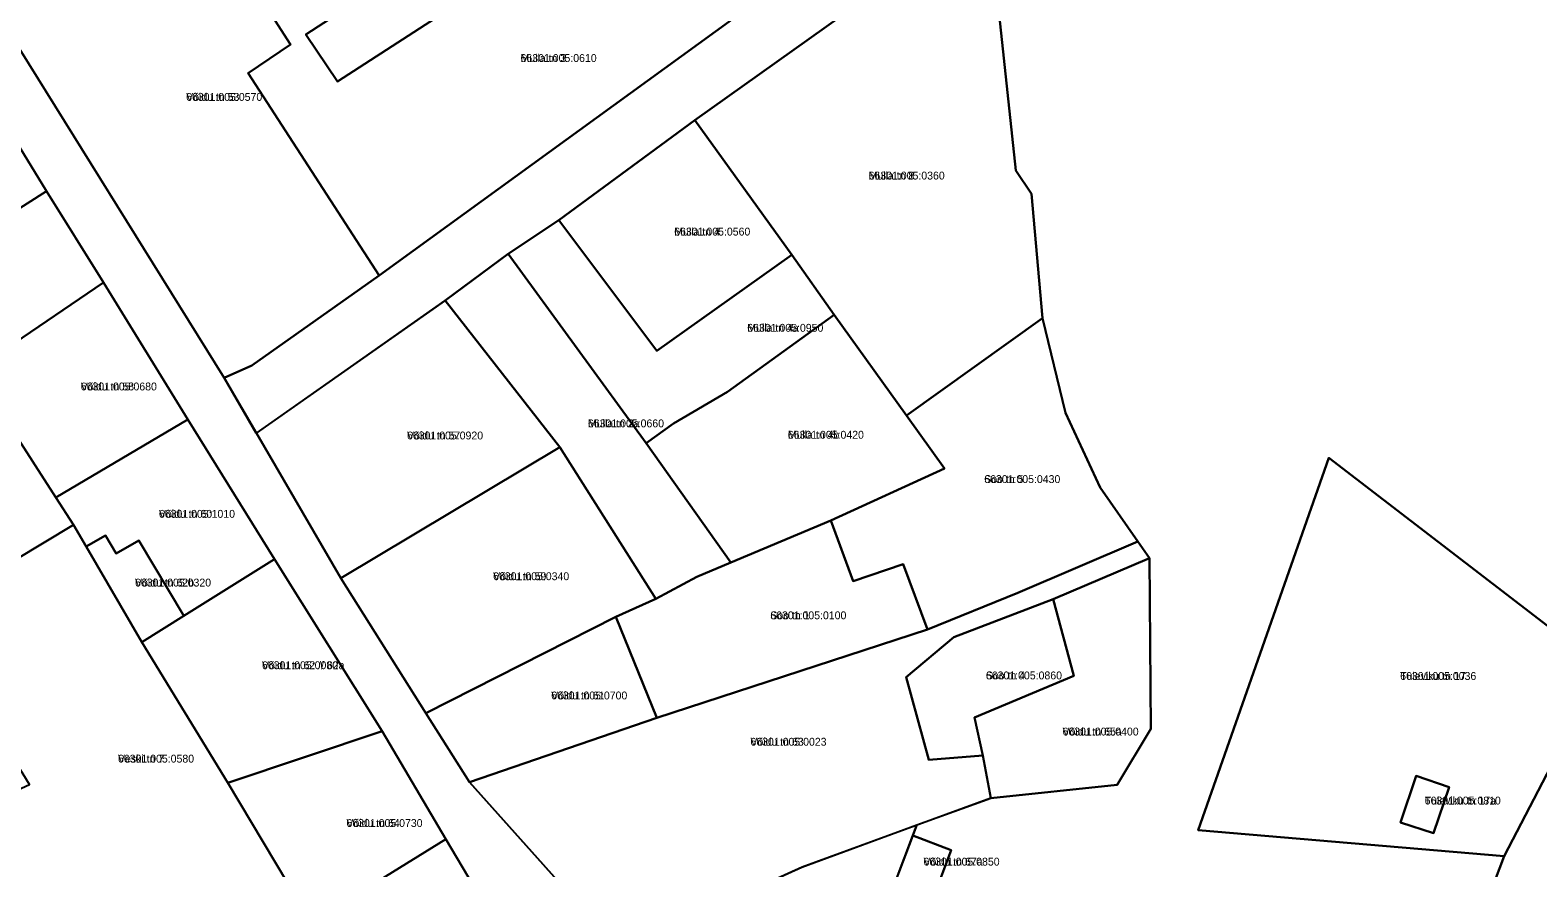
# Model space of a CAD drawing. Extents: x 632278 to 636344, y 6578401 to 6583362.
# Drawn here: x 634584.8 to 634872.1, y 6581260.6 to 6581420.2 of the extents above; entities that cross this region are included whole.
import ezdxf

# ---------------------------------------------------------------- set-up
doc = ezdxf.new("R2010")
doc.units = 0
for name, color, linetype in [('L_AADRESS', 7, 'Continuous'), ('PIIR', 7, 'Continuous'), ('TUNNUS', 7, 'Continuous')]:
    doc.layers.add(name, color=color, linetype=linetype)

msp = doc.modelspace()

# ---------------------------------------------------------------- linework, layer by layer
at = {"layer": 'PIIR'}
for points in [[(634366.06, 6581761.71), (634390.59, 6581723.7), (634395.02, 6581716.06), (634412.03, 6581688.4), (634425.76, 6581666.4), (634429.3, 6581660.73), (634446.2, 6581633.64), (634465.25, 6581603.88), (634470.5, 6581595.28), (634490.9, 6581563.22), (634504.23, 6581541.92), (634512.73, 6581527.76), (634519.26, 6581517.48), (634520.6, 6581515.15), (634532.79, 6581495.33), (634537.33, 6581488.04), (634558.25, 6581454.99), (634577.69, 6581424.67), (634621.73, 6581353.95), (634627.88, 6581343.38), (634643.98, 6581315.73), (634660.16, 6581290.01), (634668.51, 6581276.9), (634697.09, 6581244.95)], [(634840.08, 6581195.15), (634865.69, 6581262.77), (634884.36, 6581298.68), (634901.59, 6581345.02), (634942.3, 6581443.99), (634957.44, 6581478.78), (635000.2, 6581574.59), (635013.75, 6581602.14), (635016.6, 6581620.48), (635049.2, 6581605.85), (635026.32, 6581551.66), (634952.62, 6581376.82), (634946.53, 6581362.44), (634912.6, 6581276.11), (634918.34, 6581271.91), (634893.28, 6581244.04)], [(634757.02, 6581255.3), (634760.32, 6581263.95), (634752.99, 6581266.7), (634753.73, 6581268.73), (634767.88, 6581273.86), (634791.94, 6581276.36), (634798.32, 6581287.05), (634798.08, 6581319.59), (634795.84, 6581322.71), (634788.66, 6581333.04), (634782.11, 6581347.23), (634777.69, 6581365.33), (634775.6, 6581389.02), (634772.59, 6581393.46), (634767.34, 6581442.85), (634759.62, 6581513.31), (634774.57, 6581515.21), (634814.93, 6581519.91), (634841.41, 6581536.87), (634880.57, 6581561.87)], [(634767.34, 6581442.86), (634711.44, 6581403.03), (634685.54, 6581383.96), (634675.87, 6581377.55), (634663.83, 6581368.64), (634627.87, 6581343.39), (634621.72, 6581353.95), (634627.04, 6581356.26), (634651.31, 6581373.43), (634725.1, 6581427.07)], [(634674.56, 6581248.21), (634663.99, 6581266.03), (634651.83, 6581286.57), (634631.34, 6581319.38), (634614.8, 6581345.96), (634598.74, 6581372.09), (634587.89, 6581389.49), (634576.29, 6581408.42)], [(634884.36, 6581298.68), (634832.26, 6581338.69), (634807.36, 6581267.76), (634865.69, 6581262.77), (634840.08, 6581195.15)]]:
    msp.add_lwpolyline(points, dxfattribs=at)
for points in [[(634637.29, 6581419.37), (634652.51, 6581429.29), (634678.14, 6581446.22), (634706.81, 6581465.37), (634737.46, 6581485.56), (634726.44, 6581431.65), (634711.98, 6581454.81), (634643.37, 6581410.37)], [(634632.85, 6581459.43), (634644.18, 6581442.06), (634626.13, 6581430.34), (634634.36, 6581417.47), (634626.35, 6581412.01), (634651.31, 6581373.42), (634627.04, 6581356.26), (634621.73, 6581353.95), (634577.69, 6581424.67)], [(634626.35, 6581412.01), (634634.36, 6581417.47), (634626.13, 6581430.34), (634644.18, 6581442.06), (634652.51, 6581429.29), (634637.29, 6581419.37), (634643.37, 6581410.37), (634711.98, 6581454.81), (634726.44, 6581431.65), (634725.11, 6581427.06), (634651.31, 6581373.42)], [(634767.34, 6581442.85), (634772.59, 6581393.46), (634775.6, 6581389.02), (634777.69, 6581365.33), (634751.77, 6581346.77), (634738.02, 6581365.95), (634729.95, 6581377.35), (634711.44, 6581403.03)], [(634525.11, 6581374.37), (634532.54, 6581380.8), (634559.72, 6581397.71), (634576.29, 6581408.42), (634587.89, 6581389.49), (634536.03, 6581356.5)], [(634685.55, 6581383.96), (634711.44, 6581403.03), (634729.95, 6581377.35), (634704.17, 6581359.06)], [(634457.03, 6581288.49), (634440.97, 6581301.84), (634453.47, 6581309.82), (634459.09, 6581310.07), (634464.01, 6581312.99), (634485.72, 6581326.53), (634536.03, 6581356.5), (634587.89, 6581389.49), (634598.74, 6581372.09), (634574.04, 6581355.3), (634576.25, 6581351.88), (634497.3, 6581304.94), (634513.34, 6581278.43), (634510.93, 6581277.01), (634506.61, 6581274.76), (634493.5, 6581299.63), (634488.7, 6581300.88), (634472.64, 6581296.87)], [(634675.87, 6581377.55), (634685.55, 6581383.96), (634704.17, 6581359.06), (634729.95, 6581377.35), (634738.02, 6581365.95), (634717.67, 6581351.25), (634707.35, 6581345.25), (634702.18, 6581341.47)], [(634663.83, 6581368.64), (634675.87, 6581377.55), (634702.18, 6581341.47), (634718.32, 6581318.71), (634711.85, 6581315.98), (634704.03, 6581311.84), (634685.74, 6581340.73)], [(634576.25, 6581351.88), (634574.04, 6581355.3), (634598.74, 6581372.09), (634614.8, 6581345.96), (634589.69, 6581331.11)], [(634627.88, 6581343.38), (634663.83, 6581368.64), (634685.74, 6581340.73), (634643.98, 6581315.73)], [(634702.18, 6581341.47), (634707.35, 6581345.25), (634717.67, 6581351.25), (634738.02, 6581365.95), (634751.77, 6581346.77), (634759.03, 6581336.66), (634737.34, 6581326.74), (634718.32, 6581318.71)], [(634751.77, 6581346.77), (634777.69, 6581365.33), (634782.11, 6581347.23), (634788.66, 6581333.04), (634795.84, 6581322.71), (634773, 6581312.97), (634755.76, 6581305.99), (634751.17, 6581318.45), (634741.6, 6581315.18), (634737.34, 6581326.74), (634759.03, 6581336.66)], [(634513.34, 6581278.43), (634497.3, 6581304.94), (634576.25, 6581351.88), (634589.69, 6581331.11), (634593.05, 6581325.91), (634564.67, 6581308.89), (634547.35, 6581298.51)], [(634601.14, 6581320.45), (634599.16, 6581323.89), (634595.46, 6581321.77), (634593.05, 6581325.91), (634589.69, 6581331.11), (634614.8, 6581345.96), (634631.34, 6581319.38), (634614.05, 6581308.55), (634605.49, 6581322.94)], [(634643.98, 6581315.73), (634685.74, 6581340.73), (634704.03, 6581311.84), (634696.41, 6581308.4), (634660.16, 6581290.01)], [(634832.26, 6581338.69), (634884.36, 6581298.68), (634865.69, 6581262.77), (634807.36, 6581267.76)], [(634574.9, 6581247.39), (634566.68, 6581268.15), (634584.63, 6581276.42), (634564.67, 6581308.89), (634593.05, 6581325.91), (634595.46, 6581321.77), (634606.06, 6581303.55), (634622.45, 6581276.78), (634638.34, 6581250.11), (634612.24, 6581234.15), (634597.13, 6581256.23)], [(634696.41, 6581308.4), (634704.03, 6581311.84), (634711.85, 6581315.98), (634718.32, 6581318.71), (634737.34, 6581326.74), (634741.6, 6581315.18), (634751.17, 6581318.45), (634755.76, 6581305.99), (634704.2, 6581289.11)], [(634599.16, 6581323.89), (634601.14, 6581320.45), (634605.49, 6581322.94), (634614.05, 6581308.55), (634606.06, 6581303.55), (634595.46, 6581321.77)], [(634668.51, 6581276.9), (634704.2, 6581289.11), (634755.76, 6581305.99), (634773, 6581312.97), (634795.84, 6581322.71), (634798.08, 6581319.59), (634779.73, 6581311.78), (634760.78, 6581304.51), (634751.7, 6581296.87), (634756.06, 6581281.16), (634766.34, 6581281.97), (634767.88, 6581273.86), (634731.89, 6581260.67), (634697.11, 6581244.94)], [(634767.88, 6581273.86), (634766.34, 6581281.97), (634764.72, 6581289.23), (634783.65, 6581297.16), (634779.73, 6581311.78), (634798.08, 6581319.59), (634798.32, 6581287.05), (634791.94, 6581276.36)], [(634614.05, 6581308.55), (634631.34, 6581319.38), (634651.83, 6581286.57), (634622.45, 6581276.78), (634606.06, 6581303.55)], [(634766.34, 6581281.97), (634756.06, 6581281.16), (634751.7, 6581296.87), (634760.78, 6581304.51), (634779.73, 6581311.78), (634783.65, 6581297.16), (634764.72, 6581289.23)], [(634660.16, 6581290.01), (634696.41, 6581308.4), (634704.2, 6581289.11), (634668.51, 6581276.9)], [(634622.45, 6581276.78), (634651.83, 6581286.57), (634663.99, 6581266.03), (634638.34, 6581250.11)], [(634855.17, 6581275.9), (634852.2, 6581267.19), (634845.89, 6581269.22), (634848.91, 6581278.07)], [(634848.91, 6581278.07), (634845.89, 6581269.22), (634852.2, 6581267.19), (634855.17, 6581275.9)], [(634722.43, 6581256.43), (634731.85, 6581260.7), (634753.73, 6581268.73), (634752.99, 6581266.7), (634749.71, 6581258.04), (634757.02, 6581255.3), (634753.1, 6581245.04), (634742.28, 6581238.5), (634733.22, 6581233.04)], [(634670.88, 6581242.13), (634644.79, 6581236.69), (634638.34, 6581250.11), (634663.99, 6581266.03), (634674.56, 6581248.21)], [(634752.99, 6581266.7), (634760.32, 6581263.95), (634757.02, 6581255.3), (634749.71, 6581257.96)]]:
    msp.add_lwpolyline(points, close=True, dxfattribs=at)

# ---------------------------------------------------------------- texts
at = {"layer": 'L_AADRESS'}
for s, p in [('Mulla tn 3', (634678.23, 6581414.12)), ('Võidu tn 53', (634614.5, 6581406.71)), ('Mulla tn 8', (634744.56, 6581391.72)), ('Mulla tn 4', (634707.51, 6581381.04)), ('Mulla tn 4a', (634721.43, 6581362.71)), ('Võidu tn 58', (634594.42, 6581351.53)), ('Mulla tn 2a', (634691.07, 6581344.5)), ('Võidu tn 57', (634656.59, 6581342.19)), ('Mulla tn 4b', (634729.16, 6581342.33)), ('Soo tn 5', (634766.59, 6581333.88)), ('Võidu tn 60', (634609.31, 6581327.26)), ('Võidu tn 59', (634673, 6581315.37)), ('Võidu tn 62b', (634604.75, 6581314.16)), ('Soo tn 1', (634725.82, 6581307.92)), ('Võidu tn 62 // 62a', (634628.95, 6581298.41)), ('Soo tn 4', (634766.91, 6581296.47)), ('Tuleviku tn 17', (634845.86, 6581296.36)), ('Võidu tn 61', (634684.07, 6581292.65)), ('Võidu tn 63', (634722.04, 6581283.83)), ('Võidu tn 65a', (634781.52, 6581285.77)), ('Veski tn 7', (634601.51, 6581280.61)), ('Tuleviku tn 17a', (634850.53, 6581272.62)), ('Võidu tn 64', (634645.05, 6581268.34)), ('Võidu tn 67a', (634755.02, 6581260.98))]:
    msp.add_text(s, height=1.5, dxfattribs=at).set_placement(p)
at = {"layer": 'TUNNUS'}
for s, p in [('66301:005:0610', (634678.23, 6581414.12)), ('66301:005:0570', (634614.5, 6581406.71)), ('66301:005:0360', (634744.56, 6581391.72)), ('66301:005:0560', (634707.51, 6581381.04)), ('66301:005:0950', (634721.43, 6581362.71)), ('66301:005:0680', (634594.42, 6581351.53)), ('66301:005:0660', (634691.07, 6581344.5)), ('66301:005:0920', (634656.59, 6581342.19)), ('66301:005:0420', (634729.16, 6581342.33)), ('66301:005:0430', (634766.59, 6581333.88)), ('66301:005:1010', (634609.31, 6581327.26)), ('66301:005:0340', (634673, 6581315.37)), ('66301:005:0320', (634604.75, 6581314.16)), ('66301:005:0100', (634725.82, 6581307.92)), ('66301:005:0080', (634628.95, 6581298.41)), ('66301:005:0860', (634766.91, 6581296.47)), ('66301:005:0036', (634845.86, 6581296.36)), ('66301:005:0700', (634684.07, 6581292.65)), ('66301:005:0023', (634722.04, 6581283.83)), ('66301:005:0400', (634781.52, 6581285.77)), ('66301:005:0580', (634601.51, 6581280.61)), ('66301:005:0810', (634850.53, 6581272.62)), ('66301:005:0730', (634645.05, 6581268.34)), ('66301:005:0850', (634755.02, 6581260.98))]:
    msp.add_text(s, height=1.5, dxfattribs=at).set_placement(p)

doc.saveas('drawing.dxf')
